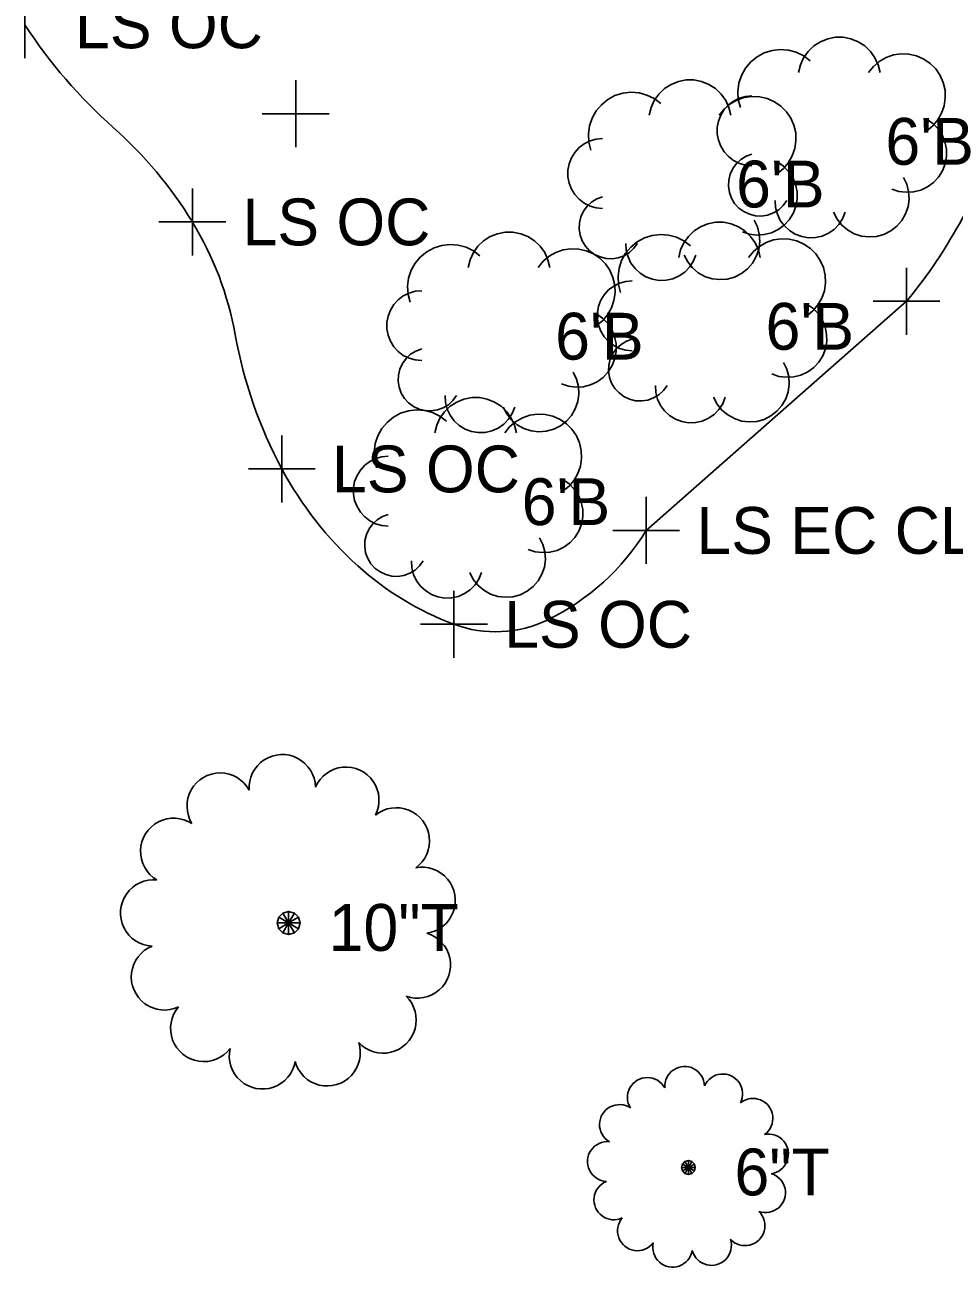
# Model space of a CAD drawing. Extents: x 1324236 to 1326110, y 459090 to 460782.
# Drawn here: x 1325401.65 to 1325429.44, y 460064.55 to 460101.69 of the extents above; entities that cross this region are included whole.
import ezdxf

# ---------------------------------------------------------------- set-up
doc = ezdxf.new("R2010")
doc.units = 0
for name, color, linetype in [('PM_X_Edge_Line', 7, 'Continuous'), ('RW_X_CL', 7, 'Continuous'), ('RW_X_Esmt_SH', 7, 'Continuous'), ('VG_X_Cells', 7, 'Continuous')]:
    doc.layers.add(name, color=color, linetype=linetype)

msp = doc.modelspace()

# ---------------------------------------------------------------- linework, layer by layer
at = {"layer": 'PM_X_Edge_Line'}
msp.add_line((1325420.234, 460086.578), (1325428.019, 460093.428), dxfattribs=at)
for centre, radius, start, end in [((1325414.429, 460110.028), 15.257, 213.1133, 228.4061), ((1325396.006, 460089.273), 12.494, 31.4952, 48.4061), ((1325416.528, 460102.946), 14.922, 320.364, 343.39), ((1325398.365, 460090.719), 9.727, 10.1494, 31.4952), ((1325421.272, 460094.819), 13.543, 190.1494, 208.2103), ((1325418.814, 460093.501), 10.754, 208.2103, 227.9367), ((1325414.185, 460090.286), 7.095, 296.008, 328.4917), ((1325417.612, 460092.169), 8.959, 227.9367, 249.57), ((1325415.731, 460087.119), 3.571, 249.57, 296.008)]:
    msp.add_arc(centre, radius, start, end, dxfattribs=at)
at = {"layer": 'RW_X_CL'}
for p, q in [((1325409.751, 460098.037), (1325409.751, 460100.037)), ((1325408.751, 460099.037), (1325410.751, 460099.037))]:
    msp.add_line(p, q, dxfattribs=at)
at = {"layer": 'RW_X_Esmt_SH'}
for p, q in [((1325401.65, 460100.693), (1325401.65, 460102.693)), ((1325406.66, 460094.801), (1325406.66, 460096.801)), ((1325405.66, 460095.801), (1325407.66, 460095.801)), ((1325428.019, 460092.428), (1325428.019, 460094.428)), ((1325427.019, 460093.428), (1325429.019, 460093.428)), ((1325409.337, 460087.417), (1325409.337, 460089.417)), ((1325408.337, 460088.417), (1325410.337, 460088.417)), ((1325420.234, 460085.578), (1325420.234, 460087.578)), ((1325419.234, 460086.578), (1325421.234, 460086.578)), ((1325414.484, 460082.773), (1325414.484, 460084.773)), ((1325413.484, 460083.773), (1325415.484, 460083.773))]:
    msp.add_line(p, q, dxfattribs=at)
at = {"layer": 'VG_X_Cells'}
for points in [[(1325427.228, 460100.268), (1325427.173, 460100.496), (1325427.076, 460100.709), (1325426.94, 460100.9), (1325426.771, 460101.062), (1325426.574, 460101.189), (1325426.356, 460101.276), (1325426.126, 460101.32), (1325425.892, 460101.32), (1325425.662, 460101.276), (1325425.445, 460101.189), (1325425.248, 460101.062), (1325425.078, 460100.9), (1325424.942, 460100.709), (1325424.845, 460100.496), (1325424.79, 460100.268)], [(1325425.138, 460100.617), (1325424.943, 460100.764), (1325424.723, 460100.871), (1325424.486, 460100.935), (1325424.242, 460100.953), (1325423.999, 460100.925), (1325423.765, 460100.852), (1325423.55, 460100.736), (1325423.36, 460100.582), (1325423.202, 460100.394), (1325423.083, 460100.18), (1325423.006, 460099.948), (1325422.974, 460099.705), (1325422.988, 460099.461), (1325423.049, 460099.223)], [(1325428.622, 460098.527), (1325428.803, 460098.674), (1325428.954, 460098.852), (1325429.07, 460099.055), (1325429.145, 460099.275), (1325429.179, 460099.506), (1325429.17, 460099.74), (1325429.117, 460099.967), (1325429.023, 460100.181), (1325428.892, 460100.373), (1325428.727, 460100.538), (1325428.534, 460100.67), (1325428.32, 460100.764), (1325428.093, 460100.816), (1325427.86, 460100.826), (1325427.629, 460100.792), (1325427.408, 460100.716), (1325427.205, 460100.601), (1325427.027, 460100.45), (1325426.88, 460100.268)], [(1325422.762, 460098.992), (1325422.707, 460099.22), (1325422.61, 460099.433), (1325422.474, 460099.624), (1325422.305, 460099.786), (1325422.108, 460099.912), (1325421.89, 460099.999), (1325421.66, 460100.044), (1325421.426, 460100.044), (1325421.196, 460099.999), (1325420.979, 460099.912), (1325420.782, 460099.786), (1325420.612, 460099.624), (1325420.476, 460099.433), (1325420.379, 460099.22), (1325420.324, 460098.992)], [(1325420.672, 460099.34), (1325420.476, 460099.487), (1325420.256, 460099.594), (1325420.02, 460099.658), (1325419.776, 460099.677), (1325419.533, 460099.649), (1325419.299, 460099.576), (1325419.084, 460099.46), (1325418.894, 460099.305), (1325418.736, 460099.118), (1325418.617, 460098.904), (1325418.54, 460098.672), (1325418.508, 460098.429), (1325418.522, 460098.184), (1325418.582, 460097.947)], [(1325423.397, 460099.572), (1325423.205, 460099.554), (1325423.019, 460099.501), (1325422.847, 460099.415), (1325422.693, 460099.299), (1325422.563, 460099.157), (1325422.461, 460098.993), (1325422.392, 460098.813), (1325422.356, 460098.623), (1325422.356, 460098.43), (1325422.392, 460098.241), (1325422.461, 460098.061), (1325422.563, 460097.897), (1325422.693, 460097.755), (1325422.847, 460097.638), (1325423.019, 460097.552), (1325423.205, 460097.5), (1325423.397, 460097.482)], [(1325424.156, 460097.25), (1325424.337, 460097.397), (1325424.488, 460097.575), (1325424.603, 460097.778), (1325424.679, 460097.999), (1325424.713, 460098.23), (1325424.704, 460098.463), (1325424.651, 460098.691), (1325424.557, 460098.904), (1325424.426, 460099.097), (1325424.261, 460099.262), (1325424.068, 460099.394), (1325423.854, 460099.487), (1325423.627, 460099.54), (1325423.393, 460099.55), (1325423.163, 460099.516), (1325422.942, 460099.44), (1325422.739, 460099.324), (1325422.561, 460099.173), (1325422.414, 460098.992)], [(1325427.577, 460096.785), (1325427.788, 460096.715), (1325428.008, 460096.686), (1325428.23, 460096.699), (1325428.446, 460096.755), (1325428.647, 460096.849), (1325428.826, 460096.981), (1325428.978, 460097.143), (1325429.096, 460097.332), (1325429.176, 460097.539), (1325429.215, 460097.758), (1325429.212, 460097.981), (1325429.168, 460098.198), (1325429.082, 460098.404), (1325428.96, 460098.589), (1325428.804, 460098.748), (1325428.622, 460098.875)], [(1325418.931, 460098.295), (1325418.739, 460098.278), (1325418.553, 460098.225), (1325418.381, 460098.139), (1325418.227, 460098.023), (1325418.097, 460097.88), (1325417.995, 460097.716), (1325417.926, 460097.536), (1325417.89, 460097.347), (1325417.89, 460097.154), (1325417.926, 460096.964), (1325417.995, 460096.785), (1325418.097, 460096.621), (1325418.227, 460096.478), (1325418.381, 460096.362), (1325418.553, 460096.276), (1325418.739, 460096.223), (1325418.931, 460096.205)], [(1325423.397, 460097.83), (1325423.224, 460097.767), (1325423.066, 460097.671), (1325422.93, 460097.546), (1325422.822, 460097.397), (1325422.744, 460097.23), (1325422.7, 460097.051), (1325422.692, 460096.867), (1325422.72, 460096.684), (1325422.783, 460096.511), (1325422.879, 460096.353), (1325423.004, 460096.217), (1325423.152, 460096.108), (1325423.319, 460096.03), (1325423.499, 460095.986), (1325423.683, 460095.978), (1325423.865, 460096.006), (1325424.038, 460096.069), (1325424.196, 460096.164), (1325424.333, 460096.288), (1325424.442, 460096.437)], [(1325423.111, 460095.509), (1325423.322, 460095.439), (1325423.542, 460095.41), (1325423.764, 460095.423), (1325423.98, 460095.478), (1325424.181, 460095.573), (1325424.36, 460095.704), (1325424.512, 460095.867), (1325424.629, 460096.056), (1325424.71, 460096.263), (1325424.749, 460096.482), (1325424.746, 460096.704), (1325424.701, 460096.922), (1325424.616, 460097.127), (1325424.494, 460097.313), (1325424.338, 460097.472), (1325424.156, 460097.599)], [(1325425.835, 460096.089), (1325425.94, 460095.886), (1325426.082, 460095.708), (1325426.255, 460095.561), (1325426.454, 460095.45), (1325426.671, 460095.379), (1325426.897, 460095.352), (1325427.124, 460095.369), (1325427.344, 460095.429), (1325427.547, 460095.531), (1325427.727, 460095.671), (1325427.877, 460095.842), (1325427.991, 460096.039), (1325428.065, 460096.255), (1325428.095, 460096.481), (1325428.081, 460096.708), (1325428.024, 460096.928), (1325427.925, 460097.134)], [(1325418.931, 460096.554), (1325418.758, 460096.49), (1325418.6, 460096.394), (1325418.464, 460096.27), (1325418.355, 460096.121), (1325418.278, 460095.954), (1325418.234, 460095.774), (1325418.226, 460095.59), (1325418.254, 460095.408), (1325418.317, 460095.235), (1325418.413, 460095.077), (1325418.538, 460094.941), (1325418.686, 460094.832), (1325418.853, 460094.754), (1325419.032, 460094.71), (1325419.217, 460094.702), (1325419.399, 460094.729), (1325419.572, 460094.792), (1325419.73, 460094.888), (1325419.866, 460095.012), (1325419.976, 460095.161)], [(1325424.094, 460096.437), (1325424.105, 460096.232), (1325424.156, 460096.032), (1325424.243, 460095.846), (1325424.365, 460095.681), (1325424.516, 460095.542), (1325424.692, 460095.434), (1325424.884, 460095.362), (1325425.087, 460095.328), (1325425.292, 460095.334), (1325425.493, 460095.379), (1325425.681, 460095.462), (1325425.85, 460095.579), (1325425.994, 460095.726), (1325426.106, 460095.898), (1325426.183, 460096.089)], [(1325423.644, 460094.738), (1325423.589, 460094.966), (1325423.492, 460095.179), (1325423.356, 460095.37), (1325423.187, 460095.532), (1325422.99, 460095.658), (1325422.772, 460095.746), (1325422.542, 460095.79), (1325422.308, 460095.79), (1325422.078, 460095.746), (1325421.861, 460095.658), (1325421.664, 460095.532), (1325421.494, 460095.37), (1325421.358, 460095.179), (1325421.261, 460094.966), (1325421.206, 460094.738)], [(1325421.369, 460094.812), (1325421.474, 460094.61), (1325421.616, 460094.432), (1325421.789, 460094.284), (1325421.988, 460094.173), (1325422.205, 460094.103), (1325422.431, 460094.076), (1325422.658, 460094.092), (1325422.877, 460094.153), (1325423.081, 460094.255), (1325423.261, 460094.394), (1325423.411, 460094.566), (1325423.525, 460094.763), (1325423.599, 460094.979), (1325423.629, 460095.204), (1325423.615, 460095.432), (1325423.558, 460095.652), (1325423.459, 460095.857)], [(1325417.351, 460094.443), (1325417.296, 460094.67), (1325417.198, 460094.883), (1325417.063, 460095.074), (1325416.893, 460095.236), (1325416.696, 460095.363), (1325416.479, 460095.45), (1325416.249, 460095.494), (1325416.014, 460095.494), (1325415.784, 460095.45), (1325415.567, 460095.363), (1325415.37, 460095.236), (1325415.2, 460095.074), (1325415.065, 460094.883), (1325414.967, 460094.67), (1325414.912, 460094.443)], [(1325421.554, 460095.087), (1325421.359, 460095.233), (1325421.139, 460095.341), (1325420.902, 460095.405), (1325420.658, 460095.423), (1325420.415, 460095.395), (1325420.181, 460095.322), (1325419.966, 460095.206), (1325419.776, 460095.051), (1325419.618, 460094.864), (1325419.499, 460094.65), (1325419.422, 460094.418), (1325419.39, 460094.175), (1325419.404, 460093.931), (1325419.465, 460093.693)], [(1325425.038, 460092.997), (1325425.219, 460093.144), (1325425.37, 460093.322), (1325425.486, 460093.524), (1325425.561, 460093.745), (1325425.595, 460093.976), (1325425.586, 460094.209), (1325425.533, 460094.437), (1325425.439, 460094.651), (1325425.308, 460094.843), (1325425.143, 460095.008), (1325424.95, 460095.14), (1325424.736, 460095.234), (1325424.509, 460095.286), (1325424.276, 460095.296), (1325424.045, 460095.262), (1325423.824, 460095.186), (1325423.621, 460095.071), (1325423.443, 460094.92), (1325423.296, 460094.738)], [(1325415.261, 460094.791), (1325415.065, 460094.938), (1325414.845, 460095.045), (1325414.608, 460095.109), (1325414.364, 460095.127), (1325414.121, 460095.099), (1325413.887, 460095.026), (1325413.672, 460094.91), (1325413.482, 460094.756), (1325413.324, 460094.568), (1325413.205, 460094.354), (1325413.128, 460094.122), (1325413.096, 460093.879), (1325413.111, 460093.635), (1325413.171, 460093.398)], [(1325418.744, 460092.701), (1325418.925, 460092.848), (1325419.076, 460093.026), (1325419.192, 460093.229), (1325419.268, 460093.449), (1325419.301, 460093.68), (1325419.292, 460093.914), (1325419.239, 460094.141), (1325419.146, 460094.355), (1325419.014, 460094.548), (1325418.849, 460094.713), (1325418.656, 460094.844), (1325418.442, 460094.938), (1325418.215, 460094.991), (1325417.982, 460095), (1325417.751, 460094.966), (1325417.53, 460094.89), (1325417.327, 460094.775), (1325417.149, 460094.624), (1325417.002, 460094.443)], [(1325419.627, 460095.161), (1325419.639, 460094.955), (1325419.689, 460094.756), (1325419.777, 460094.57), (1325419.899, 460094.404), (1325420.05, 460094.265), (1325420.226, 460094.158), (1325420.418, 460094.086), (1325420.621, 460094.052), (1325420.826, 460094.058), (1325421.027, 460094.103), (1325421.215, 460094.185), (1325421.384, 460094.302), (1325421.528, 460094.45), (1325421.64, 460094.622), (1325421.717, 460094.812)], [(1325419.813, 460094.042), (1325419.621, 460094.024), (1325419.435, 460093.971), (1325419.263, 460093.885), (1325419.109, 460093.769), (1325418.979, 460093.626), (1325418.877, 460093.462), (1325418.808, 460093.283), (1325418.772, 460093.093), (1325418.772, 460092.9), (1325418.808, 460092.711), (1325418.877, 460092.531), (1325418.979, 460092.367), (1325419.109, 460092.224), (1325419.263, 460092.108), (1325419.435, 460092.022), (1325419.621, 460091.969), (1325419.813, 460091.952)], [(1325413.519, 460093.746), (1325413.327, 460093.728), (1325413.142, 460093.675), (1325412.969, 460093.589), (1325412.815, 460093.473), (1325412.685, 460093.331), (1325412.584, 460093.167), (1325412.514, 460092.987), (1325412.479, 460092.797), (1325412.479, 460092.604), (1325412.514, 460092.415), (1325412.584, 460092.235), (1325412.685, 460092.071), (1325412.815, 460091.929), (1325412.969, 460091.812), (1325413.142, 460091.727), (1325413.327, 460091.674), (1325413.519, 460091.656)], [(1325417.699, 460090.959), (1325417.91, 460090.889), (1325418.13, 460090.86), (1325418.352, 460090.874), (1325418.568, 460090.929), (1325418.769, 460091.024), (1325418.948, 460091.155), (1325419.1, 460091.318), (1325419.218, 460091.506), (1325419.298, 460091.714), (1325419.337, 460091.932), (1325419.335, 460092.155), (1325419.29, 460092.373), (1325419.205, 460092.578), (1325419.082, 460092.763), (1325418.927, 460092.923), (1325418.744, 460093.049)], [(1325423.993, 460091.255), (1325424.204, 460091.185), (1325424.424, 460091.156), (1325424.646, 460091.169), (1325424.862, 460091.224), (1325425.063, 460091.319), (1325425.242, 460091.45), (1325425.394, 460091.613), (1325425.512, 460091.802), (1325425.592, 460092.009), (1325425.631, 460092.228), (1325425.628, 460092.45), (1325425.584, 460092.668), (1325425.498, 460092.874), (1325425.376, 460093.059), (1325425.22, 460093.218), (1325425.038, 460093.345)], [(1325419.813, 460092.3), (1325419.64, 460092.237), (1325419.482, 460092.141), (1325419.346, 460092.016), (1325419.238, 460091.867), (1325419.16, 460091.7), (1325419.116, 460091.521), (1325419.108, 460091.336), (1325419.136, 460091.154), (1325419.199, 460090.981), (1325419.295, 460090.823), (1325419.42, 460090.687), (1325419.568, 460090.578), (1325419.735, 460090.5), (1325419.915, 460090.456), (1325420.099, 460090.448), (1325420.281, 460090.476), (1325420.454, 460090.538), (1325420.612, 460090.634), (1325420.749, 460090.758), (1325420.858, 460090.907)], [(1325413.519, 460092.004), (1325413.346, 460091.941), (1325413.188, 460091.845), (1325413.053, 460091.72), (1325412.944, 460091.571), (1325412.866, 460091.404), (1325412.822, 460091.225), (1325412.814, 460091.041), (1325412.843, 460090.858), (1325412.906, 460090.685), (1325413.001, 460090.527), (1325413.126, 460090.391), (1325413.275, 460090.282), (1325413.442, 460090.204), (1325413.621, 460090.16), (1325413.805, 460090.152), (1325413.987, 460090.18), (1325414.161, 460090.243), (1325414.319, 460090.338), (1325414.455, 460090.463), (1325414.564, 460090.611)], [(1325422.251, 460090.558), (1325422.356, 460090.356), (1325422.498, 460090.178), (1325422.671, 460090.031), (1325422.87, 460089.92), (1325423.087, 460089.849), (1325423.313, 460089.822), (1325423.54, 460089.839), (1325423.76, 460089.899), (1325423.963, 460090.001), (1325424.143, 460090.14), (1325424.293, 460090.312), (1325424.407, 460090.509), (1325424.481, 460090.725), (1325424.511, 460090.95), (1325424.497, 460091.178), (1325424.44, 460091.398), (1325424.341, 460091.603)], [(1325415.957, 460090.263), (1325416.062, 460090.06), (1325416.204, 460089.882), (1325416.378, 460089.735), (1325416.576, 460089.624), (1325416.793, 460089.553), (1325417.019, 460089.526), (1325417.246, 460089.543), (1325417.466, 460089.604), (1325417.67, 460089.705), (1325417.85, 460089.845), (1325418, 460090.016), (1325418.113, 460090.214), (1325418.187, 460090.429), (1325418.217, 460090.655), (1325418.204, 460090.882), (1325418.146, 460091.103), (1325418.047, 460091.308)], [(1325420.51, 460090.907), (1325420.521, 460090.701), (1325420.572, 460090.502), (1325420.659, 460090.316), (1325420.781, 460090.151), (1325420.932, 460090.012), (1325421.108, 460089.904), (1325421.3, 460089.832), (1325421.503, 460089.798), (1325421.708, 460089.804), (1325421.909, 460089.849), (1325422.097, 460089.931), (1325422.266, 460090.048), (1325422.41, 460090.196), (1325422.522, 460090.368), (1325422.599, 460090.558)], [(1325416.351, 460089.496), (1325416.296, 460089.724), (1325416.199, 460089.937), (1325416.063, 460090.128), (1325415.893, 460090.29), (1325415.696, 460090.417), (1325415.479, 460090.504), (1325415.249, 460090.548), (1325415.014, 460090.548), (1325414.784, 460090.504), (1325414.567, 460090.417), (1325414.37, 460090.29), (1325414.2, 460090.128), (1325414.065, 460089.937), (1325413.968, 460089.724), (1325413.912, 460089.496)], [(1325414.216, 460090.611), (1325414.227, 460090.406), (1325414.278, 460090.206), (1325414.366, 460090.021), (1325414.487, 460089.855), (1325414.639, 460089.716), (1325414.814, 460089.608), (1325415.006, 460089.536), (1325415.209, 460089.502), (1325415.415, 460089.508), (1325415.615, 460089.553), (1325415.804, 460089.636), (1325415.972, 460089.753), (1325416.116, 460089.9), (1325416.228, 460090.072), (1325416.306, 460090.263)], [(1325414.261, 460089.845), (1325414.065, 460089.992), (1325413.845, 460090.099), (1325413.609, 460090.163), (1325413.364, 460090.181), (1325413.121, 460090.153), (1325412.888, 460090.08), (1325412.672, 460089.964), (1325412.482, 460089.81), (1325412.324, 460089.622), (1325412.205, 460089.408), (1325412.128, 460089.176), (1325412.096, 460088.933), (1325412.111, 460088.689), (1325412.171, 460088.451)], [(1325417.744, 460087.755), (1325417.925, 460087.902), (1325418.076, 460088.08), (1325418.192, 460088.283), (1325418.268, 460088.503), (1325418.302, 460088.734), (1325418.292, 460088.968), (1325418.239, 460089.195), (1325418.146, 460089.409), (1325418.014, 460089.601), (1325417.849, 460089.766), (1325417.656, 460089.898), (1325417.443, 460089.992), (1325417.215, 460090.044), (1325416.982, 460090.054), (1325416.751, 460090.02), (1325416.53, 460089.944), (1325416.327, 460089.829), (1325416.149, 460089.678), (1325416.002, 460089.496)], [(1325412.519, 460088.8), (1325412.327, 460088.782), (1325412.142, 460088.729), (1325411.969, 460088.643), (1325411.815, 460088.527), (1325411.685, 460088.385), (1325411.584, 460088.221), (1325411.514, 460088.041), (1325411.479, 460087.851), (1325411.479, 460087.658), (1325411.514, 460087.469), (1325411.584, 460087.289), (1325411.685, 460087.125), (1325411.815, 460086.983), (1325411.969, 460086.866), (1325412.142, 460086.78), (1325412.327, 460086.728), (1325412.519, 460086.71)], [(1325416.699, 460086.013), (1325416.91, 460085.943), (1325417.131, 460085.914), (1325417.352, 460085.927), (1325417.568, 460085.983), (1325417.769, 460086.077), (1325417.949, 460086.209), (1325418.1, 460086.371), (1325418.218, 460086.56), (1325418.298, 460086.767), (1325418.337, 460086.986), (1325418.335, 460087.209), (1325418.29, 460087.426), (1325418.205, 460087.632), (1325418.082, 460087.817), (1325417.927, 460087.976), (1325417.744, 460088.103)], [(1325412.519, 460087.058), (1325412.346, 460086.995), (1325412.189, 460086.899), (1325412.053, 460086.774), (1325411.944, 460086.625), (1325411.866, 460086.458), (1325411.822, 460086.279), (1325411.815, 460086.095), (1325411.843, 460085.912), (1325411.906, 460085.739), (1325412.001, 460085.581), (1325412.126, 460085.445), (1325412.275, 460085.336), (1325412.442, 460085.258), (1325412.621, 460085.214), (1325412.805, 460085.206), (1325412.987, 460085.234), (1325413.161, 460085.297), (1325413.319, 460085.392), (1325413.455, 460085.516), (1325413.564, 460085.665)], [(1325414.957, 460085.317), (1325415.062, 460085.114), (1325415.204, 460084.936), (1325415.378, 460084.789), (1325415.577, 460084.678), (1325415.793, 460084.607), (1325416.019, 460084.58), (1325416.246, 460084.597), (1325416.466, 460084.657), (1325416.67, 460084.759), (1325416.85, 460084.899), (1325417, 460085.07), (1325417.113, 460085.267), (1325417.187, 460085.483), (1325417.217, 460085.709), (1325417.204, 460085.936), (1325417.146, 460086.156), (1325417.047, 460086.362)], [(1325413.216, 460085.665), (1325413.227, 460085.46), (1325413.278, 460085.26), (1325413.366, 460085.074), (1325413.487, 460084.909), (1325413.639, 460084.77), (1325413.814, 460084.662), (1325414.006, 460084.59), (1325414.209, 460084.556), (1325414.415, 460084.562), (1325414.615, 460084.607), (1325414.804, 460084.69), (1325414.973, 460084.807), (1325415.116, 460084.954), (1325415.228, 460085.126), (1325415.306, 460085.317)]]:
    msp.add_lwpolyline(points, dxfattribs=at)
for points in [[(1325409.539, 460075.187), (1325409.539, 460074.843), (1325409.539, 460074.843), (1325409.368, 460075.141)], [(1325409.711, 460075.141), (1325409.539, 460074.843), (1325409.539, 460074.843), (1325409.539, 460075.187)], [(1325409.242, 460075.015), (1325409.539, 460074.843), (1325409.539, 460074.843), (1325409.196, 460074.843)], [(1325409.196, 460074.843), (1325409.539, 460074.843), (1325409.539, 460074.843), (1325409.242, 460074.672)], [(1325409.368, 460075.141), (1325409.539, 460074.843), (1325409.539, 460074.843), (1325409.242, 460075.015)], [(1325409.242, 460074.672), (1325409.539, 460074.843), (1325409.539, 460074.843), (1325409.368, 460074.546)], [(1325409.368, 460074.546), (1325409.539, 460074.843), (1325409.539, 460074.843), (1325409.539, 460074.5)], [(1325409.837, 460075.015), (1325409.539, 460074.843), (1325409.539, 460074.843), (1325409.711, 460075.141)], [(1325409.883, 460074.843), (1325409.539, 460074.843), (1325409.539, 460074.843), (1325409.837, 460075.015)], [(1325409.539, 460074.5), (1325409.539, 460074.843), (1325409.539, 460074.843), (1325409.711, 460074.546)], [(1325409.711, 460074.546), (1325409.539, 460074.843), (1325409.539, 460074.843), (1325409.837, 460074.672)], [(1325409.837, 460074.672), (1325409.539, 460074.843), (1325409.539, 460074.843), (1325409.883, 460074.843)], [(1325421.316, 460067.636), (1325421.495, 460067.533), (1325421.495, 460067.533), (1325421.289, 460067.533)], [(1325421.289, 460067.533), (1325421.495, 460067.533), (1325421.495, 460067.533), (1325421.316, 460067.43)], [(1325421.392, 460067.712), (1325421.495, 460067.533), (1325421.495, 460067.533), (1325421.316, 460067.636)], [(1325421.316, 460067.43), (1325421.495, 460067.533), (1325421.495, 460067.533), (1325421.392, 460067.355)], [(1325421.495, 460067.739), (1325421.495, 460067.533), (1325421.495, 460067.533), (1325421.392, 460067.712)], [(1325421.392, 460067.355), (1325421.495, 460067.533), (1325421.495, 460067.533), (1325421.495, 460067.327)], [(1325421.598, 460067.712), (1325421.495, 460067.533), (1325421.495, 460067.533), (1325421.495, 460067.739)], [(1325421.673, 460067.636), (1325421.495, 460067.533), (1325421.495, 460067.533), (1325421.598, 460067.712)], [(1325421.701, 460067.533), (1325421.495, 460067.533), (1325421.495, 460067.533), (1325421.673, 460067.636)], [(1325421.495, 460067.327), (1325421.495, 460067.533), (1325421.495, 460067.533), (1325421.598, 460067.355)], [(1325421.598, 460067.355), (1325421.495, 460067.533), (1325421.495, 460067.533), (1325421.673, 460067.43)], [(1325421.673, 460067.43), (1325421.495, 460067.533), (1325421.495, 460067.533), (1325421.701, 460067.533)]]:
    msp.add_lwpolyline(points, close=True, dxfattribs=at)
for centre, radius, start, end in [((1325409.35, 460078.887), 0.992, 1.241, 184.1237), ((1325407.492, 460078.336), 0.992, 28.9333, 211.816), ((1325411.251, 460078.512), 0.992, 333.5487, 156.4314), ((1325412.76, 460077.297), 0.992, 305.8564, 128.7391), ((1325406.103, 460076.985), 0.992, 56.6256, 239.5083), ((1325413.531, 460075.519), 0.992, 278.1641, 101.0468), ((1325405.502, 460075.143), 0.992, 84.3179, 267.2006), ((1325413.388, 460073.586), 0.992, 250.4718, 73.3545), ((1325405.825, 460073.232), 0.992, 112.0103, 294.8929), ((1325412.363, 460071.942), 0.992, 222.7795, 45.6622), ((1325406.999, 460071.691), 0.992, 139.7026, 322.5852), ((1325410.691, 460070.962), 0.992, 195.0872, 17.9699), ((1325408.755, 460070.871), 0.992, 167.3949, 350.2776), ((1325421.381, 460069.96), 0.595, 1.241, 184.1237), ((1325420.266, 460069.629), 0.595, 28.9333, 211.816), ((1325422.522, 460069.734), 0.595, 333.5487, 156.4314), ((1325419.433, 460068.818), 0.595, 56.6256, 239.5083), ((1325423.427, 460069.005), 0.595, 305.8564, 128.7391), ((1325423.89, 460067.938), 0.595, 278.1641, 101.0468), ((1325419.072, 460067.713), 0.595, 84.3179, 267.2006), ((1325419.266, 460066.566), 0.595, 112.0103, 294.8929), ((1325423.804, 460066.779), 0.595, 250.4718, 73.3545), ((1325419.971, 460065.642), 0.595, 139.7026, 322.5852), ((1325423.189, 460065.792), 0.595, 222.7795, 45.6622), ((1325421.024, 460065.15), 0.595, 167.3949, 350.2776), ((1325422.186, 460065.204), 0.595, 195.0872, 17.9699)]:
    msp.add_arc(centre, radius, start, end, dxfattribs=at)

# ---------------------------------------------------------------- texts
at = {"layer": 'RW_X_Esmt_SH'}
for s, p in [('LS OC', (1325403.15, 460100.993)), ('LS OC', (1325408.16, 460095.101)), ('LS OC', (1325410.837, 460087.717)), ('LS EC CLS', (1325421.734, 460085.878)), ('LS OC', (1325415.984, 460083.073))]:
    msp.add_text(s, height=1.4, dxfattribs=at).set_placement(p)
at = {"layer": 'VG_X_Cells'}
for s, p in [("6'B", (1325427.388, 460097.51)), ("6'B", (1325422.922, 460096.234)), ("6'B", (1325423.804, 460091.98)), ("6'B", (1325417.51, 460091.685)), ("6'B", (1325416.51, 460086.738)), ('10"T', (1325410.736, 460074.01)), ('6"T', (1325422.874, 460066.7))]:
    msp.add_text(s, height=1.4, dxfattribs=at).set_placement(p)

doc.saveas('drawing.dxf')
